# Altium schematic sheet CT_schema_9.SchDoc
size 287 x 160 mm
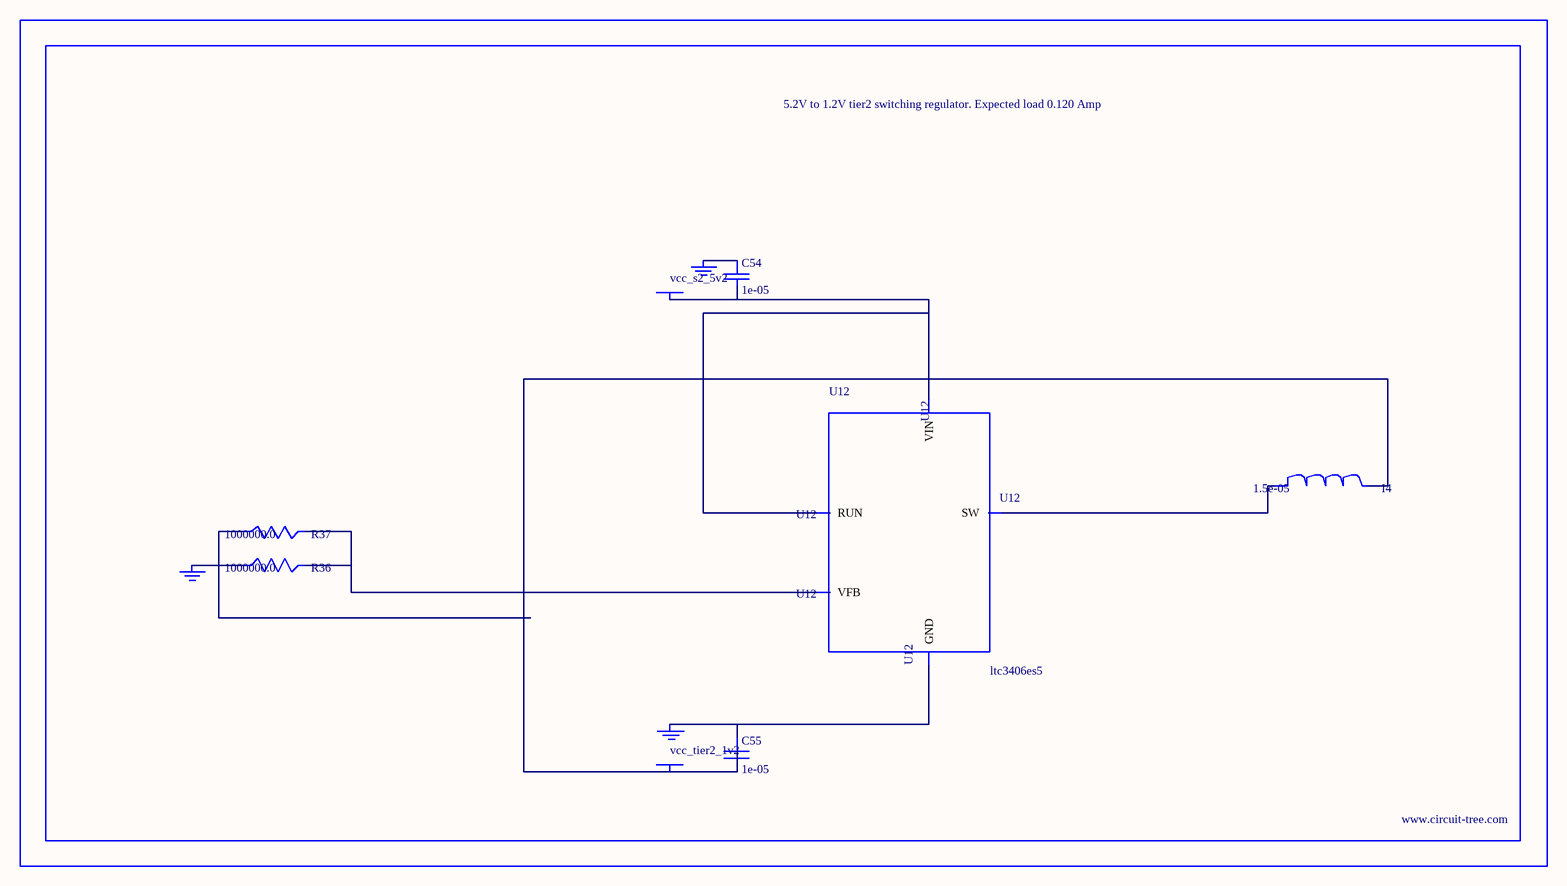
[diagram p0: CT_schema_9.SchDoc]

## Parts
BORDER8  (no value)
C54  1e-05  [C0805]
C55  1e-05  [C0805]
GND_INSTANCE_8_0  (no value)
GND_INSTANCE_8_1  (no value)
GND_INSTANCE_8_2  (no value)
I4  1.5e-05  [L1210]
POWER_INSTANCE_8_0  vcc_tier2_1v2
POWER_INSTANCE_8_1  vcc_s2_5v2
R36  1000000.0  [R0603]
R37  1000000.0  [R0603]
U12  ltc3406es5  [TSOT-23-5]

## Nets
NetC54_1: C54.1 GND_INSTANCE_8_1.0(GND)
NetC54_2: C54.2 POWER_INSTANCE_8_1.0(PWR) U12.1(RUN) U12.4(VIN)
NetC55_1: C55.1 GND_INSTANCE_8_0.0(GND) U12.2(GND)
NetC55_2: C55.2 I4.2 POWER_INSTANCE_8_0.0(PWR) R37.1
NetGND_INSTANCE_8_2_0: GND_INSTANCE_8_2.0(GND) R36.1
NetI4_1: I4.1 U12.3(SW)
NetR36_2: R36.2 R37.2 U12.5(VFB)

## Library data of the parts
BORDER8 = BORDER_PAGE8
C54 C55 = C0805C106K8RACTU
GND_INSTANCE_8_0-GND_INSTANCE_8_2 = GND
I4 = L1210R150MDWIT
POWER_INSTANCE_8_0 POWER_INSTANCE_8_1 = PWR
R36 R37 = RC0603JR-071ML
